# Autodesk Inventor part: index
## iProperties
Author: Administrateur
Created: 2001-04
Part Number: index
Material: Par défaut
Document SubType Name: Modélisation
Designer: Administrateur
Control State: 0
Master: False
Checked Out: False
PropertySet Name: Design Tracking Control
Shininess: 20.0
PropertySet Name: _Private Model Information
Length Units: 11269
Angle Units: 11283
Time Units: 11279
Mass Units: 11290
Length Display Precision: 3
Angle Display Precision: 2
Compacted: False
Density: 0.0
Volumn: 0.0
Area: 0.0
PropertySet Name: Model Information
